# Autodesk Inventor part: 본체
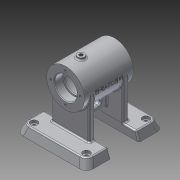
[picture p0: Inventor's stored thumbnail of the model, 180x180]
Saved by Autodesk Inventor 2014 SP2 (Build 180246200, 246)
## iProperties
Created: 2016-07
Part Number: 본체
Material: 알루미늄 6061
Document SubType Name: Modeling
Designer: 거성
Density: 2.71 g/cm^3
Appearance: 알루미늄 - 평지
Mass: 499.184 g
Surface Area: 538.786 cm^2
Volume: 184.201 cm^3
Author: 거성
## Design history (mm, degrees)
sketch "스케치1"
  geometry: C1 r 27 at (0, 0); 1 further point
  constraints: 1 centre point, 1 coincident
  dimensions: "d0" = 54 diameter of C1
extrude "돌출1" new body sketch "스케치1" distance "d1" = 70; taper "d2" = 0 deg
sketch "스케치2"
  geometry: C1 r 27 at (0, 0) reference; C2 r 16 at (0, 0)
  constraints: 1 centre point, 1 coincident
  dimensions: "d3" = 16 radius of C2
extrude "돌출2" cut sketch "스케치2" distance "d4" = 12; taper "d5" = 0 deg
sketch "스케치5"
  geometry: C1 r 16 at (0, 0) reference; C2 r 14 at (0, 0)
  constraints: 1 centre point, 1 coincident
  dimensions: "d12" = 14 radius of C2
extrude "돌출5" cut sketch "스케치5" distance "d13" = 2; taper "d14" = 0 deg
sketch "스케치6"
  geometry: C1 r 14 at (0, 0) reference; C2 r 22 at (0, 0)
  constraints: 1 centre point, 1 coincident
  dimensions: "d15" = 22 radius of C2
extrude "돌출6" cut sketch "스케치6" distance "d16" = 42; taper "d17" = 0 deg
sketch "스케치7"
  geometry: C1 r 27 at (0, 0) reference; C2 r 16 at (0, 0)
  constraints: 1 centre point, 1 coincident
  dimensions: "d18" = 16 radius of C2
extrude "돌출7" cut sketch "스케치7" distance "d19" = 12; taper "d20" = 0 deg
sketch "스케치8"
  geometry: C1 r 16 at (0, 0) reference; C2 r 14 at (0, 0)
  constraints: 1 centre point, 1 coincident
  dimensions: "d21" = 14 radius of C2
extrude "돌출8" cut sketch "스케치8" distance "d22" = 2; taper "d23" = 0 deg
node "작업 평면1"
node "작업 평면2"
sketch "스케치10"
  geometry: L1 (-58, 20)-(-58, -15) reference; L2 (-58, -90)-(-58, -55) reference; L3 (-70, -90)-(-58, -90) reference; L4 (-70, -55)-(-58, -55) reference; L5 (-70, -15)-(-58, -15) reference; L6 (-70, 20)-(-58, 20) reference; L7 (-27, 0)-(-27, -70) reference; L8 (-70, -90)-(-58, -85.632); L9 (-70, -55)-(-70, -90) reference; L10 (-70, 20)-(-58, 15.632); L11 (-70, 20)-(-70, -15) reference; 1 further point
  constraints: 4 end point, 2 point on line
  dimensions: "d34" = 110 deg angle of L9 L8; "d35" = 110 deg angle of L11 L10
extrude "돌출10" cut sketch "스케치10" stored distance "d36" = 12; taper "d37" = 0 deg
node "작업 평면3"
sketch "스케치12"
  geometry: L1 (100, 12)-(0, 12) reference; L2 (23, 70)-(23, 12); L3 (77, 70)-(77, 12); L4 (23, 12)-(77, 12); C1 r 22 at (50, 70) reference; A1 r 27 centre (50, 70) between (23, 70) and (77, 70) reference; 1 further point
  constraints: 6 end point, 2 perpendicular, 2 point on circle, 2 point on line, 1 collinear
  dimensions: "d39" = 54 distance between parallel lines of L3 L2; "d40" = 27 distance from line of point (50, 70) L2
feature "리브1" sketch "스케치12" dims "d41" = 1, "d42" = 8, "d43" = 0, "d44" = 0, "d45" = 1, "d46" = 1
node "작업 평면4"
node "작업 평면5"
sketch "스케치13"
  geometry: L1 (-58, -15)-(0, -15) reference; L2 (-27, 0)-(-27, -70) reference; L3 (-58, -55)-(0, -55) reference; L4 (-70, 20)-(-70, -15) reference; L5 (-70, -55)-(-70, -90) reference; L6 (-48, -15)-(-48, -55); L7 (-38, -27)-(-38, -43); L8 (-34.5, -27)-(-34.5, -43); L9 (-41.5, -43)-(-41.5, -27); L10 (-38, -23.5)-(-38, -46.5); L11 (-48, -35)-(-67.559, -35); L12 (-48, -15)-(-22, -15); L13 (-22, -55)-(-48, -55); L14 (-22, -14)-(-22, -56) reference; L15 (-22, -55)-(-22, -15); A1 r 3.5 centre (-38, -27) between (-34.5, -27) and (-41.5, -27); A2 r 3.5 centre (-38, -43) between (-41.5, -43) and (-34.5, -43); 3 further points
  constraints: 20 end point, 6 point on circle, 4 point on line, 4 tangent, 3 midpoint, 3 parallel, 2 centre point, 2 collinear, 1 horizontal alignment, 1 perpendicular
  dimensions: "d48" = 21 distance between parallel lines of L2 L6; "d49" = 32 distance between parallel lines of L5 L7; "d50" = 23 distance of L10.start L10.end; "d51" = 3.5 radius of A2
extrude "돌출11" join sketch "스케치13" stored distance "d53" = 8; taper "d54" = 0 deg
sketch "스케치14" dims "d55" = 42
  geometry: C1 r 27 at (0, 0) reference; 2 further points
  constraints: 1 coincident, 1 vertical alignment, 2 other
hole "구멍1" sketch "스케치14" at (0, 21) diameter "d56" = 3.242; stored, may be unused: countersink angle "d60" = 90 deg, drill point angle "d62" = 118 deg; dims "d57" = 8, "d58" = 4, "d59" = 2, "d61" = 10
node "작업 평면6"
sketch "스케치15"
  geometry: L1 (0, 0)-(15.898, -25.441); L2 (0, 0)-(0, -27); 1 further point
  constraints: 4 end point, 1 vertical, 1 vertical alignment, 1 other
  dimensions: "d66" = 32 deg angle of L1 L2; "d67" = 30 distance of L1.start L1.end
node "작업 평면7"
node "작업 평면8"
node "작업 평면9"
sketch "스케치18"
  geometry: L1 (-48, -15)-(-48, -55) reference; L2 (27, 0)-(27, -70) reference; 3 further points
  constraints: 1 horizontal alignment, 1 midpoint, 1 other
  dimensions: "d99" = 27 distance from line of point (0, -35) L2
feature "엠보싱1" sketch "스케치18" dims "d100" = 0.5, "d101" = 0
node "작업 평면10"
sketch "스케치19"
  geometry: L1 (0, 0)-(0, -27); L2 (0, 0)-(-15.898, -25.441); C1 r 1.621 at (-21, 0) reference; C2 r 1.621 at (0, -21) reference; C3 r 1.621 at (21, 0) reference; C4 r 1.621 at (0, 21) reference; C5 r 16 at (0, 0) reference; 1 further point
  constraints: 4 end point, 1 vertical, 1 vertical alignment, 1 other
  dimensions: "d102" = 32 deg angle of L1 L2; "d103" = 30 distance of L1.start L2.end
  node "투영된 루프1"
node "작업 평면11"
sketch "스케치20"
  geometry: C1 r 6 at (0, 0); 1 further point
  constraints: 1 centre point
  dimensions: "d104" = 6 radius of C1
extrude "돌출14" join sketch "스케치20" stored distance "d105" = 8; taper "d106" = 0 deg
hole "구멍4" diameter "d109" = 5.188; stored, may be unused: countersink angle "d113" = 90 deg, drill point angle "d115" = 118 deg; dims "d107" = 10, "d108" = 10, "d110" = 15, "d111" = 4, "d112" = 2, "d114" = 10
fillet "모깎기1" dims "d116" = 0.3
fillet "모깎기2" dims "d117" = 3
fillet "모깎기3" dims "d118" = 2
fillet "모깎기4" dims "d119" = 2
chamfer "모따기1" distance "d124" = 1; stored, may be unused: second distance "d125" = 2, angle "d126" = 45 deg
node "작업 평면12"
sketch "스케치21"
  geometry: L1 (-25.063, 27.017)-(74.937, 27.017); L2 (74.937, 27.017)-(74.937, -7.983); L3 (74.937, -7.983)-(-25.063, -7.983); L4 (-25.063, -7.983)-(-25.063, 27.017); L5 (47, -10)-(47, -46) reference; L6 (48.276, 2)-(1.724, 2) reference; L7 (52, -2)-(52, -6) reference; L8 (30.586, -10)-(48.276, -10) reference; L9 (30.586, -46)-(30.586, -10) reference; L10 (48.276, -46)-(30.586, -46) reference; L11 (52, -50)-(52, -54) reference; L12 (1.724, -58)-(48.276, -58) reference; L13 (-2, -50)-(-2, -54) reference; L14 (19.414, -46)-(1.724, -46) reference; L15 (19.414, -10)-(19.414, -46) reference; L16 (1.724, -10)-(19.414, -10) reference; L17 (-2, -2)-(-2, -6) reference; L18 (51.915, -42.566)-(51.915, -45.463) reference; L19 (51.915, -45.463)-(51.942, -45.463) reference; L20 (51.942, -45.463)-(51.942, -43.014) reference; L21 (51.942, -43.014)-(51.993, -43.014) reference; L22 (51.993, -43.014)-(51.993, -45.198) reference; L23 (51.993, -45.198)-(51.999, -45.198) reference; L24 (51.999, -45.198)-(51.999, -43.014) reference; L25 (51.999, -43.014)-(51.978, -43.014) reference; L26 (51.959, -42.566)-(51.915, -42.566) reference; L27 (51.966, -37.803)-(51.966, -38.834) reference; L28 (51.966, -38.834)-(51.85, -38.834) reference; L29 (51.85, -38.834)-(51.85, -39.208) reference; L30 (51.874, -39.289)-(51.963, -39.289) reference; L31 (51.963, -39.289)-(51.963, -38.834) reference; L32 (51.963, -38.834)-(51.981, -38.834) reference; L33 (51.981, -38.834)-(51.981, -37.803) reference; L34 (51.981, -37.803)-(51.966, -37.803) reference; L35 (51.869, -36.67)-(51.869, -37.071) reference; L36 (51.873, -27.512)-(51.928, -27.512) reference; L37 (51.928, -27.512)-(51.928, -25.958) reference; L38 (51.928, -25.958)-(51.895, -25.958) reference; L39 (51.895, -25.958)-(51.895, -29.526) reference; L40 (51.895, -29.526)-(51.928, -29.526) reference; L41 (51.928, -29.526)-(51.928, -27.966) reference; L42 (51.928, -27.966)-(51.873, -27.966) reference; L43 (51.873, -27.966)-(51.873, -27.512) reference; L44 (51.895, -23.122)-(51.895, -23.665) reference; L45 (51.873, -25.564)-(51.873, -25.083) reference; L46 (51.978, -24.526)-(51.978, -22.274) reference; L47 (51.873, -21.704)-(51.873, -21.223) reference; L48 (51.857, -9.147)-(51.857, -10.626) reference; L49 (51.857, -10.626)-(51.891, -10.626) reference; L50 (51.891, -10.626)-(51.891, -9.147) reference; L51 (51.891, -9.147)-(51.857, -9.147) reference; L52 (51.861, -12.939)-(51.992, -12.939) reference; L53 (51.992, -12.939)-(51.992, -14.058) reference; L54 (51.992, -14.058)-(51.999, -14.058) reference; L55 (51.999, -14.058)-(51.999, -12.939) reference; L56 (51.999, -12.939)-(51.959, -12.939) reference; L57 (51.959, -12.939)-(51.959, -12.464) reference; L58 (51.959, -12.464)-(51.833, -12.464) reference; L59 (51.833, -12.464)-(51.833, -12.769) reference; L60 (51.963, -9.269)-(51.89, -9.269) reference; L61 (51.89, -9.269)-(51.89, -13.156) reference; L62 (51.89, -13.156)-(51.853, -13.156) reference; L63 (51.853, -13.156)-(51.853, -8.807) reference; L64 (51.853, -8.807)-(51.974, -8.807) reference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; 65 further points; 1 other entity
  constraints: 10 end point, 2 midpoint, 2 parallel, 1 horizontal, 1 perpendicular, 1 vertical alignment, 86 other
  dimensions: "d128" = 35 distance of L1.end L2.end; "d129" = 100 distance of L1.start L1.end; "d130" = 55 distance of point (24.937, -27.983) point (24.937, 27.017)
extrude "돌출15" join sketch "스케치21" distance "d131" = 12; taper "d132" = 0 deg
sketch "스케치22"
  geometry: L1 (0, 0)-(35, 0) reference; L2 (0, 0)-(0, -12) reference; L3 (35, -12)-(0, -12) reference; L4 (0, -12)-(4.368, 0); 1 further point
  constraints: 2 end point, 1 point on line
  dimensions: "d133" = 110 deg angle of L3 L4
sketch "스케치23"
  geometry: L1 (0, 0)-(100, 0) reference; L2 (100, -12)-(0, -12) reference; L3 (100, 0)-(100, -12) reference; L4 (100, -12)-(95.632, 0); 1 further point
  constraints: 2 end point, 1 point on line
  dimensions: "d134" = 110 deg angle of L2 L4
extrude "돌출16" cut sketch "스케치22" stored distance "d135" = 12; taper "d136" = 0 deg
extrude "돌출17" cut sketch "스케치23" stored distance "d137" = 12; taper "d138" = 0 deg
node "작업 평면13"
node "작업 평면14"
fillet "모깎기9" dims "d140" = 10
fillet "모깎기10" dims "d141" = 2
fillet "모깎기11" dims "d178" = 2
node "작업 평면15"
sketch "스케치24"
  geometry: L1 (-2, 7)-(52, 7) reference; L2 (25, 7)-(25, -15); C1 r 5 at (25, -15)
  constraints: 2 end point, 1 centre point, 1 coincident, 1 perpendicular
  dimensions: "d180" = 22 distance of L2.start L2.end; "d181" = 10 diameter of C1
extrude "돌출18" join sketch "스케치24" stored distance "d182" = 12; taper "d183" = 0 deg
hole "구멍9" diameter "d186" = 5.188; stored, may be unused: countersink angle "d190" = 90 deg, drill point angle "d192" = 118 deg; dims "d184" = 10, "d185" = 10, "d187" = 15, "d188" = 10, "d189" = 4, "d191" = 10
fillet "모깎기12" dims "d193" = 2
sketch "스케치25"
  geometry: L1 (61.651, -21.249)-(-11.778, -21.249) reference; L2 (-25.063, -17.62)-(-25.063, 5.983) reference; L3 (65.54, -27.017)-(-15.666, -27.017) reference; L4 (24.937, -27.017)-(24.937, -14.517); L5 (-11.778, -21.249)-(61.651, -21.249); 4 further points
  constraints: 4 end point, 3 symmetric about line, 1 midpoint, 1 perpendicular
  dimensions: "d197" = 12.5 distance from line of point (-12.563, -14.517) L2; "d198" = 12.5 distance from line of point (-12.563, -14.517) L3
hole "구멍10" sketch "스케치25" at (-12.563, -14.517), (48.335, -61.324), (62.437, -14.517) diameter "d199" = 6; stored, may be unused: countersink angle "d203" = 90 deg, drill point angle "d205" = 118 deg; dims "d200" = 15, "d201" = 10, "d202" = 4, "d204" = 10
node "작업 평면16"
fillet "모깎기13" dims "d206" = 2
node "솔리드1"
mirror "대칭1"
pattern_circular "원형 패턴1" dims angle "d64" = 360 deg
mirror "대칭2"
mirror "대칭3"
mirror "대칭4"
mirror "대칭5"
mirror "대칭6"
node "투영된 루프2"
other parameters: "d33" = 0, "d47" = 0, "d98" = 27, "d127" = 0
